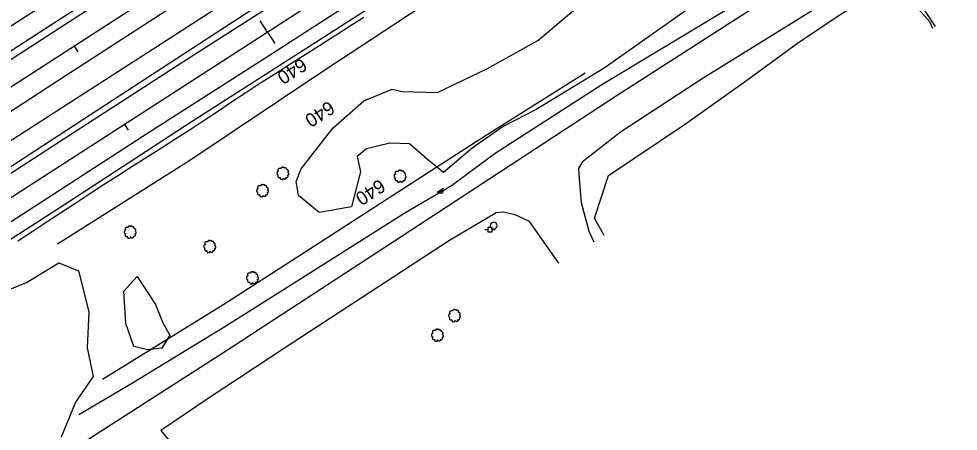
# Model space of a CAD drawing. Extents: x 1901471 to 1963503, y 756461 to 799997.
# Drawn here: x 1918267 to 1918819, y 765791 to 766034 of the extents above; entities that cross this region are included whole.
import ezdxf

# ---------------------------------------------------------------- set-up
doc = ezdxf.new("R2010")
doc.units = 0
for name, color, linetype in [('Default', 7, 'Continuous'), ('RD_DTM_BkLn1', 7, 'Continuous'), ('RD_EX_Bldg', 7, 'Continuous'), ('RD_EX_BldgApp', 7, 'Continuous'), ('RD_EX_Fence_Other', 7, 'Continuous'), ('RD_EX_H2O', 7, 'Continuous'), ('RD_EX_Road', 7, 'Continuous'), ('RD_EX_UT', 7, 'Continuous'), ('RD_EX_VEG', 7, 'Continuous'), ('RD_HC_Cl', 7, 'Continuous'), ('RD_HC_Data_Tic', 7, 'Continuous'), ('RD_HC_TX_Sta50', 7, 'Continuous')]:
    doc.layers.add(name, color=color, linetype=linetype)

# ---------------------------------------------------------------- blocks, each defined once
blk = doc.blocks.new('PP')
at = {"layer": 'RD_EX_UT'}
for p, q in [((2.490916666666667, 2.5090833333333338), (-2.5090833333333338, 2.5090833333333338)), ((-2.5090833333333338, 2.5090833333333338), (-2.5090833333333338, -2.490916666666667)), ((2.490916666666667, -2.490916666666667), (2.490916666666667, 2.5090833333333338)), ((-5.940166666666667, -0.053333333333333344), (-2.4710000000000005, -0.053333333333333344)), ((-2.5090833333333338, -2.490916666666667), (2.490916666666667, -2.490916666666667)), ((2.4194166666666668, -0.053333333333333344), (6.0598333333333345, -0.053333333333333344))]:
    blk.add_line(p, q, dxfattribs=at)
blk = doc.blocks.new('T2')
at = {"layer": 'RD_EX_VEG'}
for points in [[(0.05233333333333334, 7.213166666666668), (-0.24750000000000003, 7.238166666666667), (-0.5723333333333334, 7.138166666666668), (-0.8222500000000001, 7.038250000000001), (-1.0471666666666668, 6.963250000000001), (-1.2720833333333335, 6.863250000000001), (-1.5719166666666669, 6.688416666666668), (-1.7968333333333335, 6.488416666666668), (-1.9218333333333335, 6.2385833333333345), (-1.9718333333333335, 6.013666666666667), (-2.0217500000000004, 5.738833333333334), (-2.0217500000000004, 5.563833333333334), (-2.146666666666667, 5.538833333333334), (-2.296666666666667, 5.563833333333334), (-2.5465000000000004, 5.638833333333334), (-2.796416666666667, 5.638833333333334), (-3.0463333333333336, 5.638833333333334), (-3.3961666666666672, 5.613833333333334), (-3.7460000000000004, 5.613833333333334), (-4.020833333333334, 5.563833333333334), (-4.345750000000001, 5.513916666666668), (-4.720583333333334, 5.389000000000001), (-5.0704166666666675, 5.264000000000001), (-5.37025, 5.014083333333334), (-5.620166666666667, 4.539333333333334), (-5.745166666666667, 4.189500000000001), (-5.895083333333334, 3.9395833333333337), (-5.745166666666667, 3.489833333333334), (-5.570166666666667, 3.139916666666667), (-5.545250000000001, 2.9400000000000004), (-5.470250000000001, 2.5152500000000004), (-5.37025, 2.2903333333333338), (-5.245333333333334, 2.0903333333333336), (-5.320250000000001, 2.065416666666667), (-5.695166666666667, 2.015416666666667), (-5.995000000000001, 1.9155000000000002), (-6.419833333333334, 1.6905833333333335), (-6.644750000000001, 1.465666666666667), (-6.744750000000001, 1.1407500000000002), (-6.769666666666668, 0.7909166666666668), (-6.869583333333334, 0.5910833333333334), (-6.944583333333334, 0.3161666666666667), (-6.969583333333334, 0.2411666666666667), (-7.019583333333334, -0.08366666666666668), (-6.9195833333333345, -0.5335000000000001), (-6.894583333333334, -0.8833333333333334), (-6.769666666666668, -1.1082500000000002), (-6.619750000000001, -1.2830833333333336), (-6.444833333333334, -1.5330000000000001), (-6.045000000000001, -1.7579166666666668), (-5.7201666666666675, -1.8579166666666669), (-5.520250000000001, -1.8828333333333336), (-5.695166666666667, -2.382666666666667), (-5.745166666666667, -2.7325000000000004), (-5.870083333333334, -3.132333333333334), (-5.870083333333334, -3.2072500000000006), (-5.920000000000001, -3.682083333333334), (-5.770166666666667, -4.007000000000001), (-5.695166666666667, -4.38175), (-5.520250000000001, -4.606666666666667), (-5.245333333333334, -4.906583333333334), (-4.9205000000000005, -5.131416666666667), (-4.420666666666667, -5.256416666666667), (-4.020833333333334, -5.231416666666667), (-3.4460833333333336, -5.056500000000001), (-3.1962500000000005, -4.9815000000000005), (-3.2212500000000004, -5.156416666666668), (-3.1962500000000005, -5.531333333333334), (-3.1962500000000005, -5.956083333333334), (-3.0463333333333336, -6.280916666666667), (-2.946333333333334, -6.555833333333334), (-2.796416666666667, -6.805750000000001), (-2.4715000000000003, -7.030583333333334), (-2.07175, -7.1055833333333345), (-1.6469166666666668, -7.2555000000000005), (-1.1970833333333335, -7.330500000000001), (-0.6973333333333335, -7.355500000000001), (-0.09758333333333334, -7.205583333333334), (0.17725000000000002, -7.080583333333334), (0.27725000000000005, -6.905666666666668), (0.47716666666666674, -6.530833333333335), (0.4271666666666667, -6.3059166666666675), (0.4521666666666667, -5.706166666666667), (0.5520833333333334, -5.881166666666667), (0.7270833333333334, -6.231000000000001), (1.2268333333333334, -6.530833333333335), (1.626666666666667, -6.705750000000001), (2.101416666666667, -6.8557500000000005), (2.4013333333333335, -6.930666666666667), (2.8760833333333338, -6.8557500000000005), (3.2510000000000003, -6.780750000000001), (3.6257500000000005, -6.655750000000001), (3.9256666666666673, -6.380916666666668), (4.100583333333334, -6.106000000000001), (4.1505833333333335, -5.831166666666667), (4.2255, -5.456333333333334), (4.275500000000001, -5.281416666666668)], [(4.275500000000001, -5.281416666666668), (4.200583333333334, -5.106416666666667), (4.1505833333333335, -4.856583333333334), (4.2255, -4.881583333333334), (4.4004166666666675, -4.931583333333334), (4.675333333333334, -5.056500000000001), (4.900250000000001, -5.131416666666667), (5.225083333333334, -5.106416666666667), (5.500000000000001, -5.006500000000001), (5.949750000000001, -4.731583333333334), (6.224666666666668, -4.256833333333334), (6.499500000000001, -3.8570000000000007), (6.5745000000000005, -3.5321666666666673), (6.524500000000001, -3.3072500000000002), (6.499500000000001, -2.8075000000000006), (6.299583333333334, -2.5575833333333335), (6.249583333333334, -2.432666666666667), (6.1496666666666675, -2.0328333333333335), (6.224666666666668, -1.9828333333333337), (6.499500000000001, -1.9328333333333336), (6.874333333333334, -1.8079166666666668), (7.149250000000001, -1.6830000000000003), (7.374166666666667, -1.5080000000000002), (7.449083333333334, -1.2830833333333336), (7.424166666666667, -0.8833333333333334), (7.4740833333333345, -0.48350000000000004), (7.399166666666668, -0.3335), (7.299166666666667, -0.1836666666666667), (7.224166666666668, 0.016333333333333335), (7.074250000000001, 0.16616666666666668), (6.974333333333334, 0.3161666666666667), (6.874333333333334, 0.41608333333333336), (6.749416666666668, 0.5660833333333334), (6.5745000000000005, 0.6910000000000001), (6.424583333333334, 0.7410000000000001), (6.374583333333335, 0.8909166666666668), (6.524500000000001, 1.0908333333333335), (6.5745000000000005, 1.1907500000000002), (6.599416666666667, 1.4156666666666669), (6.824416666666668, 1.7655000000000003), (6.874333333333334, 2.1653333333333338), (6.824416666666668, 2.590166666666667), (6.774416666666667, 2.8650833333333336), (6.624416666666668, 3.139916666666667), (6.424583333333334, 3.3898333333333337), (6.299583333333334, 3.5647500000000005), (6.124666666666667, 3.689666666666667), (5.799833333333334, 3.814666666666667), (5.549916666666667, 3.864583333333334), (5.200083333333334, 3.864583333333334), (5.000166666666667, 3.9145833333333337), (5.025166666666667, 3.964583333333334), (5.025166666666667, 4.1145000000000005), (5.025166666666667, 4.389416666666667), (4.950166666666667, 4.839166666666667), (4.800250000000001, 5.339), (4.800250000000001, 5.364000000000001), (4.7002500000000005, 5.613833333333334), (4.475416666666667, 5.813750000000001), (4.3005, 5.913666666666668), (4.100583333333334, 6.038666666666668), (3.850666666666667, 6.063666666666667), (3.5508333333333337, 6.063666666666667), (3.2759166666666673, 6.013666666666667), (3.0760000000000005, 5.913666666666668), (2.9010833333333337, 5.788750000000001), (2.8260833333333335, 5.938666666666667), (2.726166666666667, 6.2385833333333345), (2.676166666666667, 6.3885000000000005), (2.52625, 6.563416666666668), (2.301416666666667, 6.7633333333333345), (1.8515000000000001, 6.888250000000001), (1.2268333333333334, 6.813333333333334), (0.9269166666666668, 6.613416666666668), (0.7770000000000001, 6.438500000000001), (0.7270833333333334, 6.563416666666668), (0.5270833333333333, 6.7633333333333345), (0.4271666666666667, 6.938250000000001), (0.25225000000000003, 7.063250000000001), (0.10233333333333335, 7.163166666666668), (0.0023333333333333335, 7.213166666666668)]]:
    blk.add_spline(points, degree=3, dxfattribs=at)
blk = doc.blocks.new('OP')
at = {"layer": 'Default'}
for centre, start, end in [((7.776250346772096e-18, 0), 90.00000000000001, 270), ((-7.776250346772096e-18, 0), 270, 90)]:
    blk.add_arc(centre, 0.12700000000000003, start, end, dxfattribs=at)
blk = doc.blocks.new('SIGN')
at = {"layer": 'RD_EX_BldgApp'}
blk.add_line((-4.517166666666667, -2.0245), (4.482833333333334, -2.0245), dxfattribs=at)
blk.add_circle((-1.0416666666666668e-05, -2.0833333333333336e-05), 2.0000000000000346, dxfattribs=at)

msp = doc.modelspace()

# ---------------------------------------------------------------- linework, layer by layer
at = {"layer": 'RD_DTM_BkLn1'}
msp.add_lwpolyline([(1918266.0411082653, 765903.2097023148), (1918274.4073873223, 765908.6874139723), (1918282.7736663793, 765914.1651256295), (1918291.1399454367, 765919.642837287), (1918299.506224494, 765925.120548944), (1918307.8725035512, 765930.5982606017), (1918316.2387826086, 765936.0759722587), (1918316.802080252, 765936.4447840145), (1918325.2396027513, 765941.8120181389), (1918333.6771252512, 765947.1792522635), (1918342.1146477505, 765952.5464863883), (1918350.55217025, 765957.9137205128), (1918358.9896927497, 765963.2809546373), (1918366.739477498, 765968.2107085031), (1918375.0730966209, 765973.7379606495), (1918383.4067157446, 765979.265212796), (1918391.7403348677, 765984.7924649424), (1918400.0739539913, 765990.3197170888), (1918408.4075731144, 765995.8469692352), (1918409.6659833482, 765996.6816066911), (1918418.1129119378, 766002.0341103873), (1918426.5598405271, 766007.3866140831), (1918435.0067691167, 766012.7391177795), (1918443.4536977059, 766018.0916214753), (1918451.9006262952, 766023.4441251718), (1918452.6979132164, 766023.9493361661), (1918461.1123948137, 766029.3519857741), (1918469.5268764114, 766034.7546353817)], dxfattribs=at)
at = {"layer": 'RD_EX_Fence_Other'}
for points in [[(1917840.3000000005, 765689.1500000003), (1917934.2100000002, 765749.9500000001), (1918030.9900000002, 765812.1800000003), (1918095.1700000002, 765854.5200000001), (1918176.0400000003, 765906.7400000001), (1918269.8800000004, 765967.2000000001), (1918350.5000000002, 766019.1800000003), (1918430.7900000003, 766071.1600000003), (1918511.2500000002, 766123.1400000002), (1918578.4900000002, 766166.6300000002), (1918618.6300000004, 766192.5000000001), (1918650.9500000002, 766213.3900000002), (1918672.8100000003, 766227.3400000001), (1918713.1200000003, 766253.2900000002), (1918791.4600000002, 766304.4500000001), (1918859.0200000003, 766347.7800000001)], [(1918315.7700000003, 765821.9000000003), (1918387.1600000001, 765865.9200000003), (1918437.7200000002, 765898.4000000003), (1918488.64, 765931.4100000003), (1918538.2500000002, 765963.3500000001), (1918599.64, 766001.9000000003)]]:
    msp.add_lwpolyline(points, dxfattribs=at)
at = {"layer": 'RD_EX_H2O'}
for points in [[(1917917.0100000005, 765756.1800000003), (1917959.64, 765783.5400000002), (1918098.39, 765872.6900000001), (1918287.8600000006, 765996.2400000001), (1918529.1500000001, 766152.4500000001), (1918659.8500000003, 766234.9300000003), (1918778.64, 766313.1200000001), (1918886.5000000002, 766381.7500000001), (1919007.2700000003, 766460.2000000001), (1919101.8500000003, 766522.0200000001), (1919206.4800000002, 766588.8500000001), (1919279.2100000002, 766635.6100000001)], [(1918301.9600000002, 765801.1300000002), (1918333.5900000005, 765819.6700000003), (1918387.7900000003, 765852.7100000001), (1918418.0100000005, 765871.8500000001), (1918493.5700000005, 765919.7000000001), (1918521.1700000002, 765935.7200000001), (1918546.7600000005, 765954.6600000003), (1918609.4200000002, 765995.1600000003), (1918681.1500000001, 766038.1700000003), (1918723.2600000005, 766068.3900000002), (1918801.0300000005, 766114.6300000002), (1918859.8600000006, 766152.2100000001), (1918953.9500000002, 766213.56), (1919000.9000000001, 766246.0000000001), (1919039.9800000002, 766268.4600000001), (1919080.0800000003, 766295.8700000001), (1919113.3200000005, 766316.0100000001), (1919169.3300000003, 766352.9900000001), (1919205.6000000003, 766375.7500000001), (1919269.0700000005, 766416.9600000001), (1919297.6800000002, 766435.6900000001), (1919410.6700000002, 766508.2000000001), (1919466.9200000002, 766542.7900000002)], [(1918289.4300000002, 765901.33), (1918366.5900000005, 765950.2500000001), (1918445.3700000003, 766002.9500000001), (1918517.6100000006, 766050.5400000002), (1918625.4600000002, 766120.1400000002), (1918719.4500000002, 766180.5400000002), (1918816.6100000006, 766244.3700000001), (1918909.6700000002, 766304.3400000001)]]:
    msp.add_lwpolyline(points, dxfattribs=at)
at = {"layer": 'RD_EX_Road'}
for points in [[(1918306.6100000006, 765760.82), (1918309.8100000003, 765765.9400000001), (1918297.5300000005, 765780.07), (1918389.3500000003, 765839.0300000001), (1918486.39, 765902.2900000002), (1918618.4300000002, 765988.7300000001), (1918754.7800000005, 766076.4100000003), (1918895.4300000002, 766167.1500000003), (1919049.5900000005, 766266.8), (1919182.5500000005, 766353.55), (1919299.2500000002, 766428.6300000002), (1919473.4900000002, 766541.2300000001), (1919612.2300000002, 766632.0200000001), (1919830.2900000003, 766770.7600000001), (1919972.0800000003, 766862.1100000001), (1920034.2600000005, 766896.5100000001), (1920082.3500000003, 766919.1800000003), (1920134.3100000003, 766939.9100000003), (1920176.0400000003, 766954.55), (1920231.8700000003, 766969.8900000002), (1920265.5900000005, 766976.2500000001), (1920274.0800000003, 766977.8400000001)], [(1917768.9700000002, 765692.9000000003), (1917871.4900000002, 765758.82), (1917977.7000000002, 765827.6100000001), (1918085.7600000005, 765897.6400000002), (1918100.1100000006, 765906.7600000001), (1918152.2700000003, 765939.6600000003), (1918221.4100000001, 765983.7600000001), (1918349.1800000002, 766066.4600000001), (1918434.2000000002, 766121.7900000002), (1918541.4500000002, 766190.57), (1918668.7300000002, 766273.5100000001), (1918763.0300000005, 766333.4800000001), (1918863.2000000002, 766399.08)], [(1917792.14, 765712.07), (1917872.1000000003, 765763.4400000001), (1917964.9900000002, 765823.4100000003), (1918051.7200000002, 765879.4900000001), (1918099.4900000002, 765910.3500000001), (1918168.3700000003, 765954.7200000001), (1918239.0300000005, 766000.1700000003), (1918315.9000000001, 766050.0300000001), (1918389.8300000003, 766097.7600000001), (1918475.1800000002, 766152.8400000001), (1918551.8800000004, 766202.5400000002), (1918626.7900000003, 766250.2700000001), (1918698.9300000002, 766296.8600000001), (1918758.6600000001, 766335.3), (1918840.0900000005, 766388.2600000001)], [(1917862.2600000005, 765688.7000000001), (1917948.1700000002, 765744.1600000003), (1918048.64, 765809.06), (1918099.7000000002, 765842.1700000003), (1918160.3700000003, 765881.4400000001), (1918238.0500000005, 765931.4600000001), (1918308.8800000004, 765977.4000000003), (1918384.6100000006, 766026.7700000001), (1918481.7100000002, 766090.0100000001), (1918605.9000000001, 766169.0000000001), (1918684.89, 766219.83), (1918755.5600000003, 766266.2600000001), (1918829.9800000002, 766313.8400000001)], [(1918868.1600000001, 766305.6800000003), (1918774.6500000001, 766245.05), (1918704.4800000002, 766199.9200000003), (1918605.0900000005, 766135.2200000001), (1918508.3100000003, 766073.1200000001), (1918411.3700000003, 766010.3700000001), (1918342.9900000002, 765966.7100000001), (1918262.2100000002, 765914.2400000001), (1918174.4100000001, 765857.8600000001), (1918134.2600000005, 765832.1500000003), (1918100.1100000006, 765809.1600000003), (1918069.5600000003, 765789.7800000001), (1917980.3600000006, 765732.06), (1917892.4000000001, 765675.58), (1917788.2400000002, 765608.0100000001)], [(1917832.5300000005, 765664.7100000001), (1917929.7200000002, 765727.9600000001), (1918012.7600000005, 765781.8900000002), (1918099.9000000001, 765837.8700000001), (1918194.4800000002, 765899.1500000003), (1918287.0100000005, 765959.2900000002), (1918363.0600000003, 766008.33), (1918440.4200000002, 766058.0200000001), (1918517.7800000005, 766107.8800000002), (1918599.5400000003, 766160.5100000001), (1918660.2500000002, 766199.7600000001), (1918753.2700000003, 766259.57), (1918827.5300000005, 766307.8)], [(1918876.3200000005, 766301.1900000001), (1918792.9300000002, 766247.0900000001), (1918704.4800000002, 766190.3800000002), (1918625.1600000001, 766138.56), (1918536.5400000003, 766081.0300000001), (1918452.8200000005, 766027.2600000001), (1918369.1000000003, 765973.81), (1918291.2600000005, 765922.9800000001), (1918169.0200000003, 765844.3900000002), (1918086.3700000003, 765790.9100000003), (1918012.7600000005, 765743.1400000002), (1917920.7000000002, 765683.7800000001), (1917827.6100000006, 765623.6000000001)], [(1918805.6700000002, 766029.2400000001), (1918791.5100000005, 766050.55), (1918781.9800000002, 766062.3800000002), (1918780.2700000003, 766064.7300000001), (1918778.0200000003, 766065.9100000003), (1918774.9200000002, 766065.05), (1918750.8300000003, 766049.6400000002), (1918669.0200000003, 765998.83), (1918620.5200000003, 765967.08), (1918597.8200000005, 765949.4100000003), (1918595.6700000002, 765945.6700000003), (1918596.2100000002, 765939.56), (1918597.39, 765925.7000000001), (1918601.8800000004, 765908.7800000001), (1918604.6800000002, 765902.57)], [(1918584.2200000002, 765890.07), (1918566.9800000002, 765914.56), (1918558.5200000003, 765918.4100000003), (1918551.4500000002, 765920.0200000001), (1918547.2800000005, 765919.5900000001), (1918519.9700000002, 765903.4200000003), (1918422.8600000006, 765840.0400000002), (1918378.6300000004, 765810.8600000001), (1918350.1500000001, 765791.6400000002), (1918358.8200000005, 765781.31), (1918324.9900000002, 765758.3900000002), (1918315.6700000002, 765753.1400000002), (1918310.3600000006, 765750.5400000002)]]:
    msp.add_lwpolyline(points, dxfattribs=at)
at = {"layer": 'RD_EX_VEG'}
for points in [[(1918610.8200000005, 765906.32), (1918605.1500000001, 765916.4200000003), (1918613.3600000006, 765941.55), (1918658.6300000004, 765971.8900000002), (1918693.9500000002, 765997.0100000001), (1918724.5500000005, 766019.4000000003), (1918749.6700000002, 766036.1900000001), (1918770.8100000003, 766049.1300000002), (1918785.9900000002, 766050.3700000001), (1918802.1500000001, 766032.2100000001), (1918803.9500000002, 766028.1200000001)], [(1918662.6100000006, 766041.0400000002), (1918610.8700000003, 766004.7300000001), (1918571.3200000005, 765980.6000000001), (1918551.4200000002, 765970.3800000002), (1918533.2600000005, 765957.6900000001), (1918516.3500000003, 765943.2700000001), (1918506.89, 765950.9800000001), (1918496.4500000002, 765960.1800000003), (1918484.7600000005, 765960.6800000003), (1918471.0800000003, 765957.2000000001), (1918465.6000000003, 765952.7200000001), (1918467.5900000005, 765943.7600000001), (1918462.3700000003, 765923.1200000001), (1918443.2200000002, 765919.8800000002), (1918431.0300000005, 765929.83), (1918429.7800000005, 765938.0400000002), (1918432.7700000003, 765945.5000000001), (1918440.9800000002, 765956.1000000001), (1918451.4300000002, 765969.5300000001), (1918469.5900000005, 765985.4500000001), (1918486.2500000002, 765992.2700000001), (1918491.9700000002, 765991.0200000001), (1918512.8600000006, 765990.2800000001), (1918542.2200000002, 766004.4600000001), (1918571.8200000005, 766020.8700000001), (1918598.1800000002, 766043.1400000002)], [(1918120.9500000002, 765777.6100000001), (1918161.1800000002, 765814.7700000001), (1918187.9000000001, 765833.5000000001), (1918213.1300000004, 765847.0200000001), (1918243.4800000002, 765867.4200000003), (1918271.0900000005, 765878.6100000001), (1918290.2400000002, 765890.3), (1918301.6900000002, 765885.58), (1918307.9000000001, 765861.4500000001), (1918306.9100000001, 765840.31), (1918310.39, 765823.3900000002), (1918299.9500000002, 765808.2200000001), (1918291.4900000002, 765787.82)]]:
    msp.add_lwpolyline(points, dxfattribs=at)
msp.add_lwpolyline([(1918334.2700000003, 765841.05), (1918329.5500000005, 765854.4900000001), (1918328.4600000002, 765873.6400000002), (1918336.3200000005, 765882.1000000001), (1918346.9600000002, 765865.6800000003), (1918351.4300000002, 765854.9800000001), (1918355.4100000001, 765847.7700000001), (1918350.6900000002, 765840.06), (1918342.2300000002, 765839.06)], close=True, dxfattribs=at)
at = {"layer": 'RD_HC_Cl'}
for p, q in [((1926729.5176193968, 771495.9286460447), (1917217.2707724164, 765354.9153898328)), ((1926745.7566169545, 771470.7766377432), (1917232.2344163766, 765328.8252854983)), ((1925391.9794752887, 770532.94101177), (1917300.1886650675, 765307.3052403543))]:
    msp.add_line(p, q, dxfattribs=at)
at = {"layer": 'RD_HC_Data_Tic'}
for p, q in [((1918412.8670364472, 766025.8670563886), (1918408.5270161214, 766032.5874896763)), ((1918412.8670364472, 766025.8670563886), (1918417.207056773, 766019.146623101)), ((1918299.1112762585, 766017.6033882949), (1918301.2808299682, 766014.2428769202)), ((1918328.8616203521, 765971.6168023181), (1918331.0316305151, 765968.2565856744))]:
    msp.add_line(p, q, dxfattribs=at)

# ---------------------------------------------------------------- block references
at = {"layer": 'Default', "xscale": 0.5039370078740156, "yscale": 0.5039370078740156}
msp.add_blockref('PP', (1918543.7300000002, 765909.7600000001), dxfattribs=at)
at = {"layer": 'RD_EX_Bldg', "xscale": 0.5039370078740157, "yscale": 0.5039370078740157, "rotation": -148.626995}
msp.add_blockref('SIGN', (1918515.0400000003, 765931.9200000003), dxfattribs=at)
at = {"layer": 'RD_EX_UT', "xscale": 15.748031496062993, "yscale": 15.748031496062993}
msp.add_blockref('OP', (1918545.9100000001, 765912.1400000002), dxfattribs=at)
at = {"layer": 'RD_EX_VEG', "xscale": 0.4921259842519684, "yscale": 0.4921259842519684}
for p in [(1918421.8300000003, 765942.9100000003), (1918490.7300000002, 765941.1700000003), (1918409.89, 765932.7100000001), (1918332.0300000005, 765908.3400000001), (1918378.8000000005, 765899.8800000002), (1918403.9200000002, 765881.4700000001), (1918522.7800000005, 765859.2200000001), (1918512.7100000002, 765847.7300000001)]:
    msp.add_blockref('T2', p, dxfattribs=at)

# ---------------------------------------------------------------- texts
at = {"layer": 'RD_HC_TX_Sta50'}
for rotation, p in [(212.8458901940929, (1918432.753903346, 766011.0682190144)), (212.84637793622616, (1918449.0395922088, 765985.8455830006)), (212.85416067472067, (1918478.7942487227, 765939.8793627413))]:
    msp.add_text('640', height=8.000000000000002, rotation=rotation, dxfattribs=at).set_placement(p)

doc.saveas('drawing.dxf')
